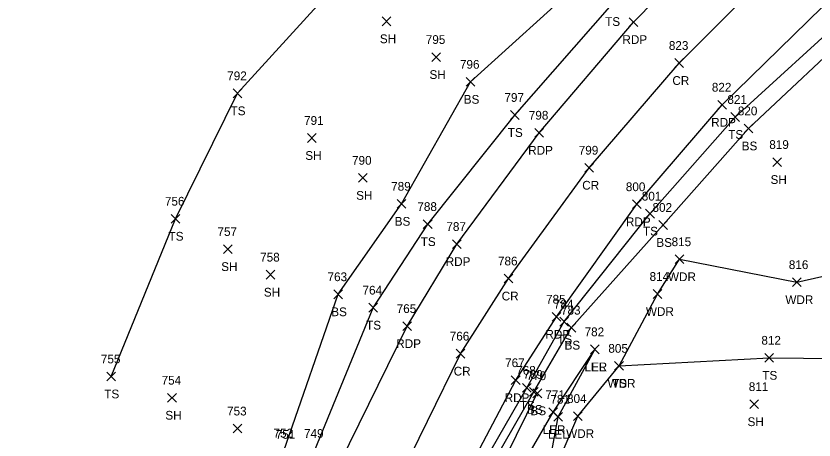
# Model space of a CAD drawing. Extents: x 1586965 to 1590952, y 716317 to 720029.
# Drawn here: x 1587122.8 to 1587304.9, y 719562.4 to 719659.2 of the extents above; entities that cross this region are included whole.
import ezdxf

# ---------------------------------------------------------------- set-up
doc = ezdxf.new("R2010")
doc.units = 0
for name, color, linetype in [('D_I', 7, 'Continuous'), ('L_A', 7, 'Continuous'), ('L_I', 7, 'Continuous'), ('L_TIC', 7, 'Continuous'), ('LARO', 7, 'Continuous'), ('LAWA', 7, 'Continuous'), ('LELB', 7, 'Continuous'), ('P_A', 7, 'Continuous'), ('P_I', 7, 'Continuous'), ('P_TIC', 7, 'Continuous'), ('PET', 7, 'Continuous'), ('PRC', 7, 'Continuous')]:
    doc.layers.add(name, color=color, linetype=linetype)

msp = doc.modelspace()

# ---------------------------------------------------------------- linework, layer by layer
at = {"layer": 'L_TIC'}
for points in [[(1587206.36, 719657.02), (1587208.36, 719659.02)], [(1587208.36, 719657.02), (1587206.36, 719659.02)], [(1587217.68, 719648.85), (1587219.68, 719650.85)], [(1587219.68, 719648.85), (1587217.68, 719650.85)], [(1587225.54, 719643.19), (1587227.54, 719645.19)], [(1587227.54, 719643.19), (1587225.54, 719645.19)], [(1587172.36, 719640.57), (1587174.36, 719642.57)], [(1587174.36, 719640.57), (1587172.36, 719642.57)], [(1587235.63, 719635.62), (1587237.63, 719637.62)], [(1587237.63, 719635.62), (1587235.63, 719637.62)], [(1587285.95, 719635.16), (1587287.95, 719637.16)], [(1587287.95, 719635.16), (1587285.95, 719637.16)], [(1587288.99, 719632.55), (1587290.99, 719634.55)], [(1587290.99, 719632.55), (1587288.99, 719634.55)], [(1587189.33, 719630.37), (1587191.33, 719632.37)], [(1587191.33, 719630.37), (1587189.33, 719632.37)], [(1587295.53, 719624.87), (1587297.53, 719626.87)], [(1587297.53, 719624.87), (1587295.53, 719626.87)], [(1587200.94, 719621.26), (1587202.94, 719623.26)], [(1587202.94, 719621.26), (1587200.94, 719623.26)], [(1587209.79, 719615.33), (1587211.79, 719617.33)], [(1587211.79, 719615.33), (1587209.79, 719617.33)], [(1587158.2, 719611.92), (1587160.2, 719613.92)], [(1587160.2, 719611.92), (1587158.2, 719613.92)], [(1587266.49, 719613.08), (1587268.49, 719615.08)], [(1587268.49, 719613.08), (1587266.49, 719615.08)], [(1587215.76, 719610.7), (1587217.76, 719612.7)], [(1587217.76, 719610.7), (1587215.76, 719612.7)], [(1587269.51, 719610.5), (1587271.51, 719612.5)], [(1587271.51, 719610.5), (1587269.51, 719612.5)], [(1587170.15, 719604.99), (1587172.15, 719606.99)], [(1587172.15, 719604.99), (1587170.15, 719606.99)], [(1587273.23, 719602.67), (1587275.23, 719604.67)], [(1587275.23, 719602.67), (1587273.23, 719604.67)], [(1587179.88, 719599.15), (1587181.88, 719601.15)], [(1587181.88, 719599.15), (1587179.88, 719601.15)], [(1587300.03, 719597.43), (1587302.03, 719599.43)], [(1587302.03, 719597.43), (1587300.03, 719599.43)], [(1587195.31, 719594.67), (1587197.31, 719596.67)], [(1587197.31, 719594.67), (1587195.31, 719596.67)], [(1587268.2, 719594.73), (1587270.2, 719596.73)], [(1587270.2, 719594.73), (1587268.2, 719596.73)], [(1587203.29, 719591.61), (1587205.29, 719593.61)], [(1587205.29, 719591.61), (1587203.29, 719593.61)], [(1587246.92, 719588.42), (1587248.92, 719590.42)], [(1587248.92, 719588.42), (1587246.92, 719590.42)], [(1587248.54, 719587.04), (1587250.54, 719589.04)], [(1587250.54, 719587.04), (1587248.54, 719589.04)], [(1587253.93, 719582.09), (1587255.93, 719584.09)], [(1587255.93, 719582.09), (1587253.93, 719584.09)], [(1587253.93, 719582.09), (1587255.93, 719584.09)], [(1587255.93, 719582.09), (1587253.93, 719584.09)], [(1587293.72, 719580.16), (1587295.72, 719582.16)], [(1587295.72, 719580.16), (1587293.72, 719582.16)], [(1587259.43, 719578.32), (1587261.43, 719580.32)], [(1587261.43, 719578.32), (1587259.43, 719580.32)], [(1587259.43, 719578.32), (1587261.43, 719580.32)], [(1587261.43, 719578.32), (1587259.43, 719580.32)], [(1587143.53, 719575.9), (1587145.53, 719577.9)], [(1587145.53, 719575.9), (1587143.53, 719577.9)], [(1587238.38, 719573.3), (1587240.38, 719575.3)], [(1587240.38, 719573.3), (1587238.38, 719575.3)], [(1587239.99, 719572.37), (1587241.99, 719574.37)], [(1587241.99, 719572.37), (1587239.99, 719574.37)], [(1587240.78, 719572.06), (1587242.78, 719574.06)], [(1587242.78, 719572.06), (1587240.78, 719574.06)], [(1587157.39, 719571.04), (1587159.39, 719573.04)], [(1587159.39, 719571.04), (1587157.39, 719573.04)], [(1587244.4, 719567.76), (1587246.4, 719569.76)], [(1587246.4, 719567.76), (1587244.4, 719569.76)], [(1587290.27, 719569.57), (1587292.27, 719571.57)], [(1587292.27, 719569.57), (1587290.27, 719571.57)], [(1587245.56, 719566.69), (1587247.56, 719568.69)], [(1587247.56, 719566.69), (1587245.56, 719568.69)], [(1587250, 719566.85), (1587252, 719568.85)], [(1587252, 719566.85), (1587250, 719568.85)], [(1587172.33, 719564), (1587174.33, 719566)], [(1587174.33, 719564), (1587172.33, 719566)]]:
    msp.add_lwpolyline(points, dxfattribs=at)
at = {"layer": 'LARO'}
for points in [[(1587207.88, 719470.84), (1587213.47, 719490.13), (1587222.49, 719522.34), (1587230.49, 719542.98), (1587245.4, 719568.76), (1587254.93, 719583.09)], [(1587209.04, 719470.1), (1587216.07, 719486.45), (1587218.68, 719500.05), (1587226.66, 719522.84), (1587234.63, 719543.06), (1587243.18, 719549.48), (1587246.56, 719567.69), (1587254.93, 719583.09)]]:
    msp.add_lwpolyline(points, dxfattribs=at)
at = {"layer": 'LAWA'}
msp.add_lwpolyline([(1587171.91, 719364.5), (1587185.92, 719394.62), (1587194.51, 719437.33), (1587204.69, 719465.5), (1587209.04, 719470.1), (1587216.07, 719486.45), (1587218.68, 719500.05), (1587226.66, 719522.84), (1587234.63, 719543.06), (1587243.18, 719549.48), (1587251, 719567.85), (1587260.43, 719579.32), (1587269.2, 719595.73), (1587274.23, 719603.67), (1587301.03, 719598.43), (1587318.82, 719602.47), (1587334.94, 719606.57), (1587351.65, 719607.7), (1587367.28, 719615.21), (1587401.27, 719626.51), (1587435.01, 719634.6)], dxfattribs=at)
at = {"layer": 'LELB'}
for points in [[(1586974.22, 719201.38), (1587004.64, 719224.97), (1587038.23, 719264.63), (1587070.35, 719308.83), (1587101.6, 719349.88), (1587119.36, 719390.75), (1587135.94, 719419.64), (1587149.18, 719457.32), (1587161.88, 719497.01), (1587171.82, 719537.32), (1587183.93, 719559.95), (1587196.31, 719595.67), (1587210.79, 719616.33), (1587226.54, 719644.19), (1587252.78, 719668.03), (1587275.41, 719699.75), (1587291.25, 719715.32), (1587307.92, 719729.13), (1587319.25, 719735.05), (1587320, 719753.34), (1587323.07, 719768.88), (1587320.57, 719781.92), (1587330.74, 719804.48), (1587340.87, 719823.38)], [(1586974.22, 719201.38), (1587004.64, 719224.97), (1587038.23, 719264.63), (1587070.35, 719308.83), (1587101.6, 719349.88), (1587119.36, 719390.75), (1587135.94, 719419.64), (1587149.18, 719457.32), (1587161.88, 719497.01), (1587171.82, 719537.32), (1587183.93, 719559.95), (1587196.31, 719595.67), (1587210.79, 719616.33), (1587226.54, 719644.19), (1587252.78, 719668.03), (1587275.41, 719699.75), (1587291.25, 719715.32), (1587307.92, 719729.13), (1587319.25, 719735.05), (1587320, 719753.34), (1587323.07, 719768.88), (1587320.57, 719781.92), (1587330.74, 719804.48), (1587340.87, 719823.38)], [(1587144.53, 719576.9), (1587159.2, 719612.92), (1587173.36, 719641.57), (1587196.33, 719666.85), (1587220.14, 719694.18), (1587245.98, 719721.02), (1587255.84, 719735.21), (1587269.46, 719752.51), (1587285.85, 719779.85)], [(1587144.53, 719576.9), (1587159.2, 719612.92), (1587173.36, 719641.57), (1587196.33, 719666.85), (1587220.14, 719694.18), (1587245.98, 719721.02), (1587255.84, 719735.21), (1587269.46, 719752.51), (1587285.85, 719779.85)], [(1586978.66, 719194.77), (1587009.14, 719220.21), (1587042.41, 719260.62), (1587074.55, 719306.69), (1587105.59, 719347.25), (1587126.81, 719387.29), (1587140.39, 719417.03), (1587155.04, 719455.09), (1587167.34, 719494.49), (1587179.82, 719533.81), (1587190.9, 719559.88), (1587204.29, 719592.61), (1587216.76, 719611.7), (1587236.63, 719636.62), (1587258.85, 719661.96), (1587283.81, 719691.81), (1587311.82, 719715.76), (1587323.53, 719725.34), (1587349.89, 719742.95), (1587377.37, 719757.84), (1587414.05, 719779.22)], [(1586978.66, 719194.77), (1587009.14, 719220.21), (1587042.41, 719260.62), (1587074.55, 719306.69), (1587105.59, 719347.25), (1587126.81, 719387.29), (1587140.39, 719417.03), (1587155.04, 719455.09), (1587167.34, 719494.49), (1587179.82, 719533.81), (1587190.9, 719559.88), (1587204.29, 719592.61), (1587216.76, 719611.7), (1587236.63, 719636.62), (1587258.85, 719661.96), (1587283.81, 719691.81), (1587311.82, 719715.76), (1587323.53, 719725.34), (1587349.89, 719742.95), (1587377.37, 719757.84), (1587414.05, 719779.22)], [(1587111.95, 719287.48), (1587133.61, 719303.61), (1587148.92, 719323.42), (1587167.88, 719366.46), (1587179.01, 719397.6), (1587173.15, 719399.12), (1587186.97, 719441.05), (1587200.36, 719482.43), (1587215.71, 719524.53), (1587222.82, 719545.46), (1587239.38, 719574.3), (1587247.92, 719589.42), (1587267.49, 719614.08), (1587286.95, 719636.16), (1587313.61, 719660.46), (1587335.34, 719679.69), (1587361.68, 719697.91), (1587398.24, 719722.21), (1587438.94, 719742.74)], [(1587111.95, 719287.48), (1587133.61, 719303.61), (1587148.92, 719323.42), (1587167.88, 719366.46), (1587179.01, 719397.6), (1587173.15, 719399.12), (1587186.97, 719441.05), (1587200.36, 719482.43), (1587215.71, 719524.53), (1587222.82, 719545.46), (1587239.38, 719574.3), (1587247.92, 719589.42), (1587267.49, 719614.08), (1587286.95, 719636.16), (1587313.61, 719660.46), (1587335.34, 719679.69), (1587361.68, 719697.91), (1587398.24, 719722.21), (1587438.94, 719742.74)], [(1587178.28, 719402.93), (1587189.21, 719440.25), (1587198.32, 719468.09), (1587203.86, 719481.06), (1587218.12, 719523.56), (1587224.35, 719543.95), (1587223.87, 719544.83), (1587224.18, 719545.53), (1587225.1, 719545.69), (1587240.99, 719573.37), (1587249.54, 719588.04), (1587270.51, 719611.5), (1587289.99, 719633.55), (1587315.89, 719657.91), (1587337.85, 719676.76), (1587363.47, 719694.64), (1587400.93, 719718.94), (1587441.36, 719738.52)], [(1587178.28, 719402.93), (1587189.21, 719440.25), (1587198.32, 719468.09), (1587203.86, 719481.06), (1587218.12, 719523.56), (1587224.35, 719543.95), (1587223.87, 719544.83), (1587224.18, 719545.53), (1587225.1, 719545.69), (1587240.99, 719573.37), (1587249.54, 719588.04), (1587270.51, 719611.5), (1587289.99, 719633.55), (1587315.89, 719657.91), (1587337.85, 719676.76), (1587363.47, 719694.64), (1587400.93, 719718.94), (1587441.36, 719738.52)], [(1587260.43, 719579.32), (1587294.72, 719581.16), (1587326.04, 719580.86)], [(1587260.43, 719579.32), (1587294.72, 719581.16), (1587326.04, 719580.86)], [(1587219.68, 719523.24), (1587227.67, 719544.5), (1587241.78, 719573.06)], [(1587219.68, 719523.24), (1587227.67, 719544.5), (1587241.78, 719573.06)]]:
    msp.add_lwpolyline(points, dxfattribs=at)
at = {"layer": 'P_TIC'}
for points in [[(1587262.71, 719656.85), (1587264.71, 719658.85)], [(1587264.71, 719656.85), (1587262.71, 719658.85)], [(1587273.17, 719647.49), (1587275.17, 719649.49)], [(1587275.17, 719647.49), (1587273.17, 719649.49)], [(1587282.97, 719637.96), (1587284.97, 719639.96)], [(1587284.97, 719637.96), (1587282.97, 719639.96)], [(1587241.2, 719631.56), (1587243.2, 719633.56)], [(1587243.2, 719631.56), (1587241.2, 719633.56)], [(1587252.6, 719623.57), (1587254.6, 719625.57)], [(1587254.6, 719623.57), (1587252.6, 719625.57)], [(1587263.51, 719615.23), (1587265.51, 719617.23)], [(1587265.51, 719615.23), (1587263.51, 719617.23)], [(1587222.39, 719606.14), (1587224.39, 719608.14)], [(1587224.39, 719606.14), (1587222.39, 719608.14)], [(1587234.22, 719598.27), (1587236.22, 719600.27)], [(1587236.22, 719598.27), (1587234.22, 719600.27)], [(1587245.13, 719589.54), (1587247.13, 719591.54)], [(1587247.13, 719589.54), (1587245.13, 719591.54)], [(1587211.09, 719587.4), (1587213.09, 719589.4)], [(1587213.09, 719587.4), (1587211.09, 719589.4)], [(1587223.26, 719581.11), (1587225.26, 719583.11)], [(1587225.26, 719581.11), (1587223.26, 719583.11)], [(1587235.84, 719575.04), (1587237.84, 719577.04)], [(1587237.84, 719575.04), (1587235.84, 719577.04)]]:
    msp.add_lwpolyline(points, dxfattribs=at)
at = {"layer": 'PET'}
for points in [[(1586981.32, 719191.44), (1587010.72, 719218.17), (1587046.97, 719256.26), (1587081.9, 719302.22), (1587109.59, 719344.47), (1587130.23, 719386.19), (1587143.83, 719415.56), (1587158.67, 719453.12), (1587172.27, 719492.43), (1587186.37, 719531.4), (1587196.72, 719557.08), (1587212.09, 719588.4), (1587223.39, 719607.14), (1587242.2, 719632.56), (1587263.71, 719657.85), (1587289.89, 719684.48), (1587313.81, 719705.37), (1587345, 719730.07), (1587380.68, 719751.95), (1587418.28, 719771.56)], [(1586998.3, 719170.55), (1587031.46, 719201.5), (1587048.24, 719215.72), (1587069.37, 719240.81), (1587083.56, 719258.07), (1587104.56, 719290.21), (1587133.86, 719331.71), (1587155.62, 719372.22), (1587169, 719404.76), (1587183.27, 719443.5), (1587197.56, 719483.83), (1587211.74, 719526.3), (1587221.19, 719546.28), (1587236.84, 719576.04), (1587246.13, 719590.54), (1587264.51, 719616.23), (1587283.97, 719638.96), (1587310.1, 719664.5), (1587332.49, 719682.99), (1587358.98, 719703.31), (1587395.82, 719726.18), (1587435.88, 719747.89)]]:
    msp.add_lwpolyline(points, dxfattribs=at)
at = {"layer": 'PRC'}
msp.add_lwpolyline([(1586989.8, 719181.42), (1587021.35, 719209.83), (1587057.54, 719247.82), (1587093.64, 719295.06), (1587121.6, 719338.75), (1587145.01, 719385.55), (1587156.05, 719410.32), (1587170.73, 719448.3), (1587185.3, 719487.87), (1587199.88, 719528.69), (1587209.21, 719551.28), (1587224.26, 719582.11), (1587235.22, 719599.27), (1587253.6, 719624.57), (1587274.17, 719648.49), (1587299.95, 719674.27), (1587323.51, 719694.22), (1587352.02, 719715.49), (1587388.91, 719738.13), (1587428.57, 719759.37)], dxfattribs=at)
msp.add_lwpolyline([(1586989.8, 719181.42), (1587021.35, 719209.83), (1587057.54, 719247.82), (1587093.64, 719295.06), (1587121.6, 719338.75), (1587145.01, 719385.55), (1587156.05, 719410.32), (1587170.73, 719448.3), (1587185.3, 719487.87), (1587199.88, 719528.69), (1587209.21, 719551.28), (1587224.26, 719582.11), (1587235.22, 719599.27), (1587253.6, 719624.57), (1587274.17, 719648.49), (1587299.95, 719674.27), (1587323.51, 719694.22), (1587352.02, 719715.49), (1587388.91, 719738.13), (1587428.57, 719759.37)], dxfattribs=at)

# ---------------------------------------------------------------- texts
at = {"layer": 'D_I'}
msp.add_text('751', height=2, dxfattribs=at).set_placement((1587182.07, 719562.68))
at = {"layer": 'L_A'}
for s, p in [('TS', (1587257.26, 719656.96)), ('SH', (1587205.84, 719653.02)), ('SH', (1587217.17, 719644.85)), ('BS', (1587224.98, 719639.19)), ('TS', (1587171.77, 719636.57)), ('TS', (1587235.04, 719631.62)), ('TS', (1587285.36, 719631.16)), ('BS', (1587288.43, 719628.55)), ('SH', (1587188.82, 719626.37)), ('SH', (1587295.01, 719620.87)), ('SH', (1587200.43, 719617.26)), ('BS', (1587209.23, 719611.33)), ('TS', (1587157.61, 719607.92)), ('TS', (1587265.9, 719609.08)), ('TS', (1587215.17, 719606.7)), ('BS', (1587268.95, 719606.5)), ('SH', (1587169.63, 719600.99)), ('WDR', (1587271.59, 719598.67)), ('SH', (1587179.37, 719595.15)), ('WDR', (1587298.39, 719593.43)), ('BS', (1587194.75, 719590.67)), ('WDR', (1587266.56, 719590.73)), ('TS', (1587202.7, 719587.61)), ('TS', (1587246.32, 719584.42)), ('BS', (1587247.99, 719583.04)), ('LER', (1587252.51, 719578.09)), ('LEL', (1587252.57, 719578.09)), ('TS', (1587293.13, 719576.16)), ('WDR', (1587257.8, 719574.32)), ('TS', (1587258.84, 719574.32)), ('TS', (1587142.94, 719571.9)), ('TS', (1587237.79, 719569.3)), ('BS', (1587239.43, 719568.37)), ('BS', (1587240.22, 719568.06)), ('SH', (1587156.88, 719567.04)), ('SH', (1587289.76, 719565.57)), ('LER', (1587242.99, 719563.76)), ('LEL', (1587244.2, 719562.69)), ('WDR', (1587248.36, 719562.85))]:
    msp.add_text(s, height=2, dxfattribs=at).set_placement(p)
at = {"layer": 'L_I'}
for s, p in [('795', (1587216.32, 719652.85)), ('796', (1587224.12, 719647.19)), ('792', (1587171, 719644.57)), ('797', (1587234.27, 719639.62)), ('821', (1587285.16, 719639.16)), ('820', (1587287.54, 719636.55)), ('791', (1587188.54, 719634.37)), ('819', (1587294.72, 719628.87)), ('790', (1587199.49, 719625.26)), ('789', (1587208.42, 719619.33)), ('801', (1587265.62, 719617.08)), ('756', (1587156.78, 719615.92)), ('788', (1587214.4, 719614.7)), ('802', (1587268.07, 719614.5)), ('757', (1587168.78, 719608.99)), ('815', (1587272.43, 719606.67)), ('758', (1587178.52, 719603.15)), ('816', (1587299.18, 719601.43)), ('814', (1587267.4, 719598.73)), ('763', (1587193.9, 719598.67)), ('764', (1587201.88, 719595.61)), ('784', (1587245.55, 719592.42)), ('783', (1587247.18, 719591.04)), ('782', (1587252.57, 719586.09)), ('782', (1587252.57, 719586.09)), ('812', (1587292.92, 719584.16)), ('805', (1587257.99, 719582.32)), ('805', (1587257.99, 719582.32)), ('755', (1587142.17, 719579.9)), ('768', (1587236.97, 719577.3)), ('754', (1587156.03, 719575.04)), ('769', (1587238.57, 719576.37)), ('770', (1587239.33, 719576.06)), ('811', (1587290.04, 719573.57)), ('771', (1587243.61, 719571.76)), ('781', (1587244.77, 719570.69)), ('804', (1587248.56, 719570.85)), ('753', (1587170.97, 719568)), ('752', (1587181.56, 719562.95)), ('749', (1587188.53, 719562.88))]:
    msp.add_text(s, height=2, dxfattribs=at).set_placement(p)
at = {"layer": 'P_A'}
for s, p in [('RDP', (1587261.2, 719652.85)), ('CR', (1587272.6, 719643.49)), ('RDP', (1587281.46, 719633.96)), ('RDP', (1587239.69, 719627.56)), ('CR', (1587252.03, 719619.57)), ('RDP', (1587262, 719611.23)), ('RDP', (1587220.87, 719602.14)), ('CR', (1587233.65, 719594.27)), ('RDP', (1587243.62, 719585.54)), ('RDP', (1587209.58, 719583.4)), ('CR', (1587222.69, 719577.11)), ('RDP', (1587234.33, 719571.04))]:
    msp.add_text(s, height=2, dxfattribs=at).set_placement(p)
at = {"layer": 'P_I'}
for s, p in [('823', (1587271.8, 719651.49)), ('822', (1587281.61, 719641.96)), ('798', (1587239.84, 719635.56)), ('799', (1587251.23, 719627.57)), ('800', (1587261.98, 719619.23)), ('787', (1587221.02, 719610.14)), ('786', (1587232.8, 719602.27)), ('785', (1587243.77, 719593.54)), ('765', (1587209.68, 719591.4)), ('766', (1587221.79, 719585.11)), ('767', (1587234.43, 719579.04))]:
    msp.add_text(s, height=2, dxfattribs=at).set_placement(p)

doc.saveas('drawing.dxf')
